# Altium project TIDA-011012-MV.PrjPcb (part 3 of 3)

## Sheet TIDA-011012-MV Auxiliary Power.SchDoc
size 431 x 279 mm; Date: Not shown in title block; ApprovedBy: Not shown in title block; CheckedBy: Not shown in title block; Author: Not shown in title block; CompanyName: Not shown in title block; Engineer: Not shown in title block; Organization: Not shown in title block; Address1: Not shown in title block; Address2: Not shown in title block; Address3: Not shown in title block; Address4: Not shown in title block; DocumentNumber: 4; Revision: Use project parameter SCH_Rev; SheetNumber: 4; SheetTotal: 11; PageSetup: Record=PageOptions¦CenterHorizontal=True¦CenterVertical=True¦PrintScale=1.00¦XCorrection=1.00¦YCorrection=1.00¦PrintKind=0¦BorderSize=5000000¦LeftOffset=0¦BottomOffset=0¦Orientation=2¦PaperLength=1000¦PaperWidth=1000¦Scale=100¦PaperSource=15¦PrintQuality=600¦MediaType=1¦DitherType=10¦PaperKind=Letter¦PrintScaleMode=1
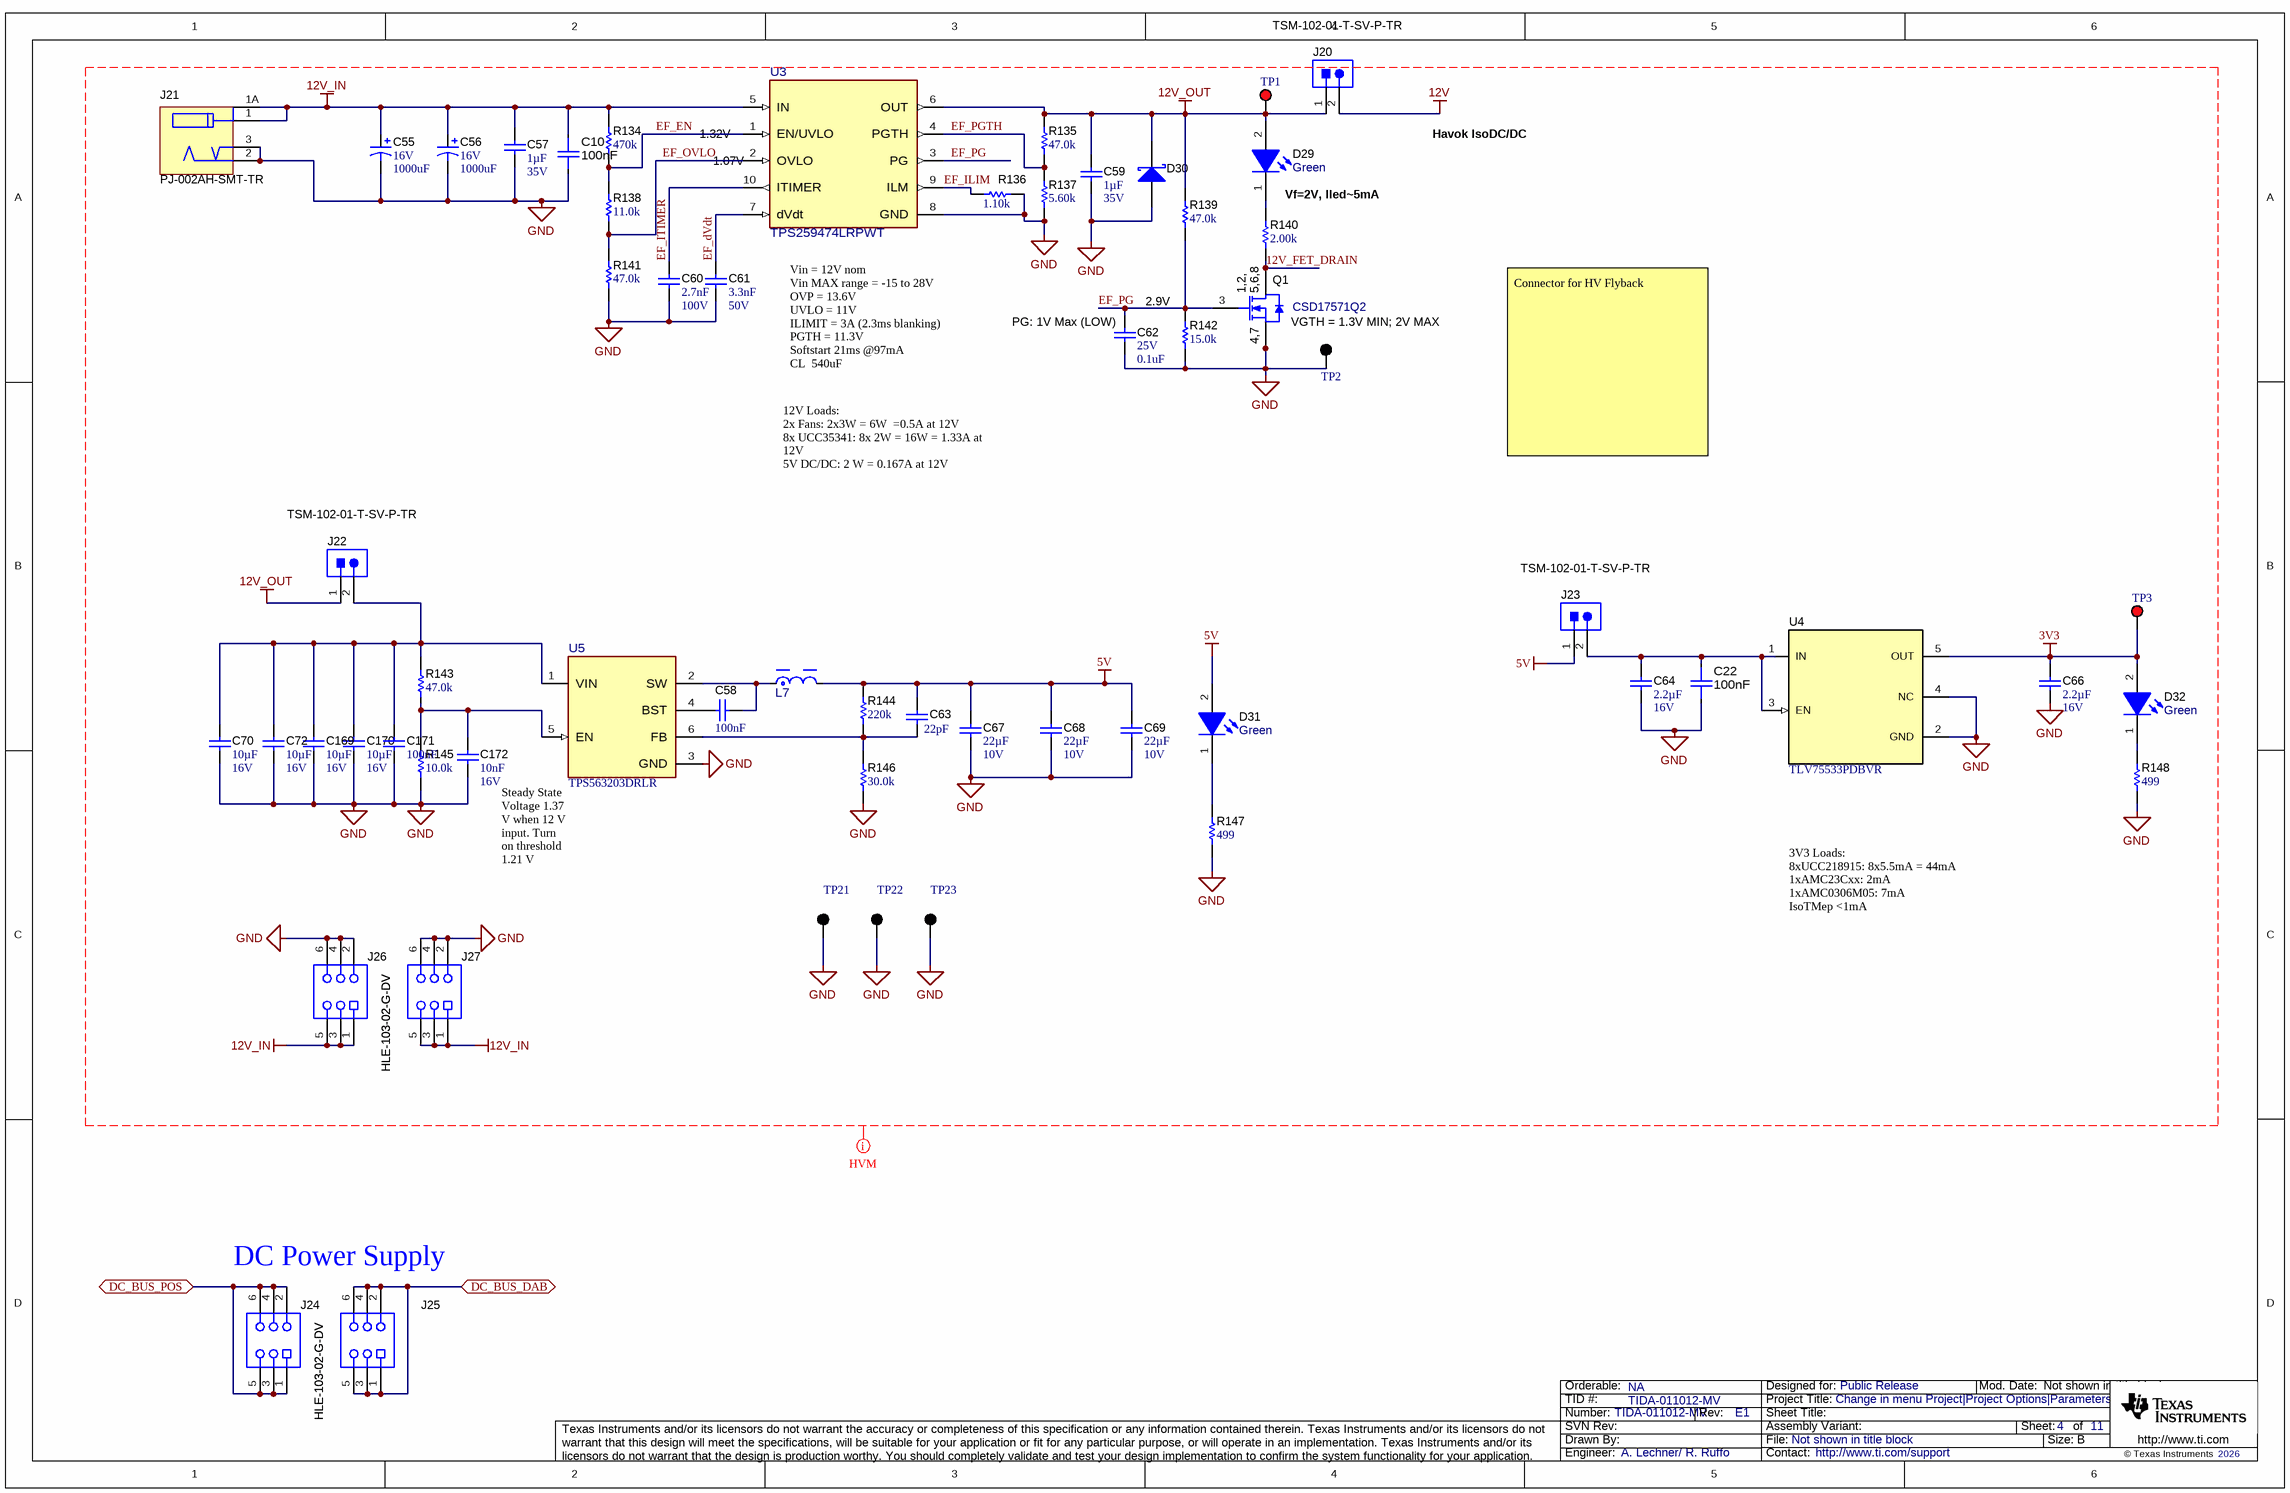
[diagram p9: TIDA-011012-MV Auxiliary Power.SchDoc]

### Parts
C10  Cap_F: 100nF  [FP-CL10B104KA8VPJC_0603-MFG]  (hidden comment: CL10B104KA8VPJC)
C22  Cap_F: 100nF  [FP-CL10B104KA8VPJC_0603-MFG]  (hidden comment: CL10B104KA8VPJC)
C55  VDC_V: 16V  ValueDisplayed: 1000uF  [CAPPR5-10x16]  (hidden comment: 16ZLJ1000MCE10X16)
C56  VDC_V: 16V  ValueDisplayed: 1000uF  [CAPPR5-10x16]  (hidden comment: 16ZLJ1000MCE10X16)
C57  Cap_F: 1µF  VDC_V: 35V  [0603]  (hidden comment: C1608X7R1V105K080AC)
C58  Cap_F: 100nF  [0603]  (hidden comment: 06033C104JAT2A)
C59  Cap_F: 1µF  VDC_V: 35V  [0603]  (hidden comment: C1608X7R1V105K080AC)
C60  Cap_F: 2.7nF  VDC_V: 100V  [0603]  (hidden comment: GRM188R72A272KA01D)
C61  Cap_F: 3.3nF  VDC_V: 50V  [0603]  (hidden comment: C0603X332K5RACTU)
C62  VDC_V: 25V  ValueDisplayed: 0.1uF  [0402L]  (hidden comment: GRM155R71E104KE14D)
C63  ValueDisplayed: 22pF  [0603]  (hidden comment: GRM1885C2A220JA01D)
C64  Cap_F: 2.2µF  VDC_V: 16V  [0603]  (hidden comment: EMK107BB7225KA-T)
C66  Cap_F: 2.2µF  VDC_V: 16V  [0603]  (hidden comment: EMK107BB7225KA-T)
C67  Cap_F: 22µF  VDC_V: 10V  [0805_HV]  (hidden comment: GRM21BZ71A226ME15L)
C68  Cap_F: 22µF  VDC_V: 10V  [0805_HV]  (hidden comment: GRM21BZ71A226ME15L)
C69  Cap_F: 22µF  VDC_V: 10V  [0805_HV]  (hidden comment: GRM21BZ71A226ME15L)
C70  Cap_F: 10µF  VDC_V: 16V  [0805_HV]  (hidden comment: EMK212BB7106KG-T)
C72  Cap_F: 10µF  VDC_V: 16V  [0805_HV]  (hidden comment: EMK212BB7106KG-T)
C169  Cap_F: 10µF  VDC_V: 16V  [0805_HV]  (hidden comment: EMK212BB7106KG-T)
C170  Cap_F: 10µF  VDC_V: 16V  [0805_HV]  (hidden comment: EMK212BB7106KG-T)
C171  Cap_F: 100nF  [0603]  (hidden comment: 06033C104JAT2A)
C172  Cap_F: 10nF  VDC_V: 16V  [0603]  (hidden comment: C0603C103K4RACTU)
D29  value Green  [WL-SMCW_GREEN]  (hidden comment: 150060VS75000)
D30  B330A-13-F  [SMA]  (value not drawn)
D31  value Green  [WL-SMCW_GREEN]  (hidden comment: 150060VS75000)
D32  value Green  [WL-SMCW_GREEN]  (hidden comment: 150060VS75000)
J20  TSM-102-01-T-SV-P-TR  [Samtec_TSM-102-01-T-SV-P-TR]
J21  PJ-002AH-SMT-TR  [CUI_PJ-002AH-SMT]
J22  TSM-102-01-T-SV-P-TR  [Samtec_TSM-102-01-T-SV-P-TR]
J23  TSM-102-01-T-SV-P-TR  [Samtec_TSM-102-01-T-SV-P-TR]
J24  HLE-103-02-G-DV  [Samtec_HLE-103-02-x-DV]
J25  HLE-103-02-G-DV  [Samtec_HLE-103-02-x-DV]
J26  HLE-103-02-G-DV  [Samtec_HLE-103-02-x-DV]
J27  HLE-103-02-G-DV  [Samtec_HLE-103-02-x-DV]
L7  74439324047  [FP-74439324047_SMD2-MFG]  (value not drawn)
Q1  CSD17571Q2  [DQK0006C]
R134  ValueDisplayed: 470k  [0603]  (hidden comment: RC0603FR-07470KL)
R135  ValueDisplayed: 47.0k  [0603]  (hidden comment: RC0603FR-0747KL)
R136  ValueDisplayed: 1.10k  [0603]  (hidden comment: RC0603FR-071K1L)
R137  ValueDisplayed: 5.60k  [0603]  (hidden comment: RC0603FR-075K6L)
R138  ValueDisplayed: 11.0k  [0603]  (hidden comment: RC0603FR-0711KL)
R139  ValueDisplayed: 47.0k  [0603]  (hidden comment: RC0603FR-0747KL)
R140  ValueDisplayed: 2.00k  [0603]  (hidden comment: RC0603FR-072KL)
R141  ValueDisplayed: 47.0k  [0603]  (hidden comment: RC0603FR-0747KL)
R142  ValueDisplayed: 15.0k  [0603]  (hidden comment: RC0603FR-0715KL)
R143  ValueDisplayed: 47.0k  [0603]  (hidden comment: RC0603FR-0747KL)
R144  ValueDisplayed: 220k  [0603]  (hidden comment: RC0603FR-07220KL)
R145  ValueDisplayed: 10.0k  [0603]  (hidden comment: RG1608P-103-B-T5)
R146  ValueDisplayed: 30.0k  [0603]  (hidden comment: RC0603FR-0730KL)
R147  ValueDisplayed: 499  [0603]  (hidden comment: CRCW0603499RFKEAC)
R148  ValueDisplayed: 499  [0603]  (hidden comment: CRCW0603499RFKEAC)
TP1  5010  [Keystone5010]  (value not drawn)
TP2  5011  [Keystone5011]  (value not drawn)
TP3  5010  [Keystone5010]  (value not drawn)
TP21  5011  [Keystone5011]  (value not drawn)
TP22  5011  [Keystone5011]  (value not drawn)
TP23  5011  [Keystone5011]  (value not drawn)
U3  TPS259474LRPWT  [RPW0010A-MFG]
U4  TLV75533PDBVR  [DBV0005A_N]
U5  TPS563203DRLR  [DRL0006A-MFG]

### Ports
DC_BUS_DAB (bidir), DC_BUS_POS (bidir)

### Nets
3V3: C66.1 D32.2(A) TP3.1 U4.5(OUT)
5V: C63.1 C67.1 C68.1 C69.1 D31.2(A) J23.1 L7.2 R144.2
12V: J20.2
12V_IN: C10.1 C55.1(+) C56.1(+) C57.1 J21.1 J21.1A J26.1 J26.3 J26.5 J27.1 J27.3 J27.5 R134.2 U3.5(IN)
12V_OUT: C59.1 D29.2(A) D30.1(K) J20.1 J22.1 R135.2 R139.2 TP1.1 U3.6(OUT)
GND: C10.2 C22.2 C55.2(-) C56.2(-) C57.2 C59.2 C60.2 C61.2 C62.2 C64.2 C66.2 C67.2 C68.2 C69.2 C70.2 C72.2 C169.2 C170.2 C171.1 C172.2 D30.2(A) J21.2 J21.3 J26.2 J26.4 J26.6 J27.2 J27.4 J27.6 Q1.4(S) Q1.7(S) R136.1 R137.1 R141.1 R142.1 R145.2 R146.1 R147.1 R148.1 TP2.1 TP21.1 TP22.1 TP23.1 U3.8(GND) U4.2(GND) U4.4(NC) U5.3(GND)
12V_FET_DRAIN: Q1.1(D) Q1.2(D) Q1.5(D) Q1.6(D) Q1.8(D) R140.1
DC_BUS_DAB: J25.1 J25.2 J25.3 J25.4 J25.5 J25.6 ; port DC_BUS_DAB
DC_BUS_POS: J24.1 J24.2 J24.3 J24.4 J24.5 J24.6 ; port DC_BUS_POS
EF_dVdt: C61.1 U3.7(dVdt)
EF_EN: R134.1 R138.2 U3.1(EN/UVLO)
EF_ILIM: R136.2 U3.9(ILM)
EF_ITIMER: C60.1 U3.10(ITIMER)
EF_OVLO: R138.1 R141.2 U3.2(OVLO)
EF_PG: C62.1 Q1.3(G) R139.1 R142.2 U3.3(PG)
EF_PGTH: R135.1 R137.2 U3.4(PGTH)
NetC22_1: C22.1 C64.1 J23.2 U4.1(IN) U4.3(EN)
NetC58_1: C58.1 U5.4(BST)
NetC58_2: C58.2 L7.1 U5.2(SW)
NetC63_2: C63.2 R144.1 R146.2 U5.6(FB)
NetC70_1: C70.1 C72.1 C169.1 C170.1 C171.2 J22.2 R143.2 U5.1(VIN)
NetC172_1: C172.1 R143.1 R145.1 U5.5(EN)
NetD29_1: D29.1(K) R140.2
NetD31_1: D31.1(K) R147.2
NetD32_1: D32.1(K) R148.2

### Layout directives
net class HVM: 3V3, 5V, 12V, 12V_FET_DRAIN, 12V_IN, 12V_OUT, EF_dVdt, EF_EN, EF_ILIM, EF_ITIMER, EF_OVLO, EF_PG, EF_PGTH, GND

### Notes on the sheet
- (near U3) 1.32V
- (near U3) 1.07V
- Havok IsoDC/DC
- Vf=2V, Iled~5mA
- 2.9V
- Vin = 12V nom
  Vin MAX range = -15 to 28V
  OVP = 13.6V
  UVLO = 11V
  ILIMIT = 3A (2.3ms blanking)
  PGTH = 11.3V
  Softstart 21ms @97mA
  CL  540uF
- (near C62) PG: 1V Max (LOW)
- VGTH = 1.3V MIN; 2V MAX
- 12V Loads:
  2x Fans: 2x3W = 6W  =0.5A at 12V
  8x UCC35341: 8x 2W = 16W = 1.33A at 12V
  5V DC/DC: 2 W = 0.167A at 12V
- Connector for HV Flyback
- (near U5) Steady State Voltage 1.37 V when 12 V input. Turn on threshold 1.21 V
- 3V3 Loads:
  8xUCC218915: 8x5.5mA = 44mA
  1xAMC23Cxx: 2mA
  1xAMC0306M05: 7mA
  IsoTMep <1mA
- DC Power Supply

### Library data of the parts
C10 C22 = CMP-0121051-1: Automotive CAP, 100㎋, 25V, ±10%, X7R, 0603, 5mm Bending; Manufacturer: Samsung; AEC Grade: Grade 1; AEC Qualified: Yes; SizeZ_mm: 0.9mm; TempCo: 15%; Value: 100nF
C55 C56 = CMP-0010289-1: CAP, AL, 1000 uF, 16 V, +/- 20%, TH; Manufacturer: Rubycon; TaMin_C: -40°C; Polarized: Y; SizeAreaWB_mm2: 144; Value1: Unknown; U/M: EA; Value: 1000uF; TaMax_C: 105°C; SizeZ_mm: 17.5; SizeX_mm: 10; Cap_Case: 10x16; SizeArea_mm2: 100; CompType: Capacitor; AEC Qualified: N; Cap_F: 1mF; AEC Category: Q200
C57 C59 = CMP-0007052-4: CAP, CERM, 1 uF, 35 V, +/- 10%, X7R, 0603; Manufacturer: TDK; TaMin_C: -55°C; Polarized: N; SizeAreaWB_mm2: 4.68; Value1: Unknown; U/M: EA; Value: 1uF; TaMax_C: 125°C; SizeZ_mm: 1; SizeX_mm: 1.6; SizeY_mm: 0.8; SizeArea_mm2: 1.28; AEC Category: Q200
C58 C171 = CMP-0006752-5: CAP, CERM, 0.1 uF, 25 V, +/- 5%, X7R, 0603; Manufacturer: AVX; TaMin_C: -55°C; ESR_ohm: 0.05; Polarized: N; SizeAreaWB_mm2: 4.68; Value1: 0.05 ohm; U/M: EA; Value: 0.1uF; TaMax_C: 125°C; SizeZ_mm: 1; SizeX_mm: 1.6; SizeY_mm: 0.8; Value2: 25V; SizeArea_mm2: 1.28; AEC Category: Q200
C60 = CMP-0007477-4: CAP, CERM, 2700 pF, 100 V, +/- 10%, X7R, 0603; Manufacturer: MuRata; TaMin_C: -55°C; Polarized: N; SizeAreaWB_mm2: 4.68; Value1: Unknown; U/M: EA; Value: 2700pF; TaMax_C: 125°C; SizeZ_mm: 1; SizeX_mm: 1.6; SizeY_mm: 0.8; SizeArea_mm2: 1.28; AEC Category: Q200
C61 = CMP-0006985-4: CAP, CERM, 3300 pF, 50 V, +/- 10%, X7R, 0603; Manufacturer: Kemet; TaMin_C: -55°C; Polarized: N; SizeAreaWB_mm2: 4.68; Value1: Unknown; U/M: EA; Value: 3300pF; TaMax_C: 125°C; SizeZ_mm: 1; SizeX_mm: 1.6; SizeY_mm: 0.8; SizeArea_mm2: 1.28; AEC Category: Q200
C62 = CMP-0006659-2: CAP, CERM, 0.1 uF, 25 V, +/- 10%, X7R, 0402; Manufacturer: MuRata; TaMin_C: -55°C; Polarized: N; SizeAreaWB_mm2: 3; Value1: Unknown; U/M: EA; Value: 0.1uF; TaMax_C: 125°C; SizeZ_mm: 0.6; SizeX_mm: 1; SizeY_mm: 0.5; Cap_Case: 0402; Cap_F: 100nF; AEC Category: Q200
C63 = CMP-0007255-4: CAP, CERM, 22 pF, 100 V, +/- 5%, C0G/NP0, 0603; Manufacturer: MuRata; TaMin_C: -55°C; Polarized: N; SizeAreaWB_mm2: 4.68; Value1: Unknown; U/M: EA; Value: 22pF; TaMax_C: 125°C; SizeZ_mm: 1; SizeX_mm: 1.6; SizeY_mm: 0.8; Value2: 100V; SizeArea_mm2: 1.28; AEC Category: Q200
C64 C66 = CMP-0007121-4: CAP, CERM, 2.2 uF, 16 V, +/- 10%, X7R, 0603; Manufacturer: Taiyo Yuden; TaMin_C: -55°C; Polarized: N; SizeAreaWB_mm2: 4.68; Value1: Unknown; U/M: EA; Value: 2.2uF; TaMax_C: 125°C; SizeZ_mm: 1; SizeX_mm: 1.6; SizeY_mm: 0.8; SizeArea_mm2: 1.28; AEC Category: Q200
C67-C69 = CMP-0008377-2: CAP, CERM, 22 uF, 10 V, +/- 20%, X7R, 0805; Manufacturer: MuRata; SizeY_mm: 1.25; Cap_Case: 0805; SizeArea_mm2: 2.5; AEC Qualified: N; AEC Category: Q200; ValueDisplayed: 22uF; TaMin_C: -55°C; SizeAreaWB_mm2: 6.75; Value1: Unknown; U/M: EA; Value: 22uF; TaMax_C: 125°C; SizeZ_mm: 1.45; SizeX_mm: 2
C70 C72 C169 C170 = CMP-0085283-1: CAP, CERM, 10 µF, 16 V,+/- 10%, X7R, 0805; Manufacturer: Taiyo Yuden; TaMin_C: -55°C; AEC Qualified: N; U/M: EA; TaMax_C: 125°C; SizeAreaWB_mm2: 6.75; SizeZ_mm: 1.45; Value: 10uF; SizeY_mm: 1.25; SizeArea_mm2: 2.5; AEC Category: Q200; SizeX_mm: 2; Cap_Case: 0805
C172 = CMP-0006853-4: CAP, CERM, 0.01 uF, 16 V, +/- 10%, X7R, 0603; Manufacturer: Kemet; TaMin_C: -55°C; Polarized: N; SizeAreaWB_mm2: 4.68; Value1: Unknown; U/M: EA; Value: 0.01uF; TaMax_C: 125°C; SizeZ_mm: 1; SizeX_mm: 1.6; SizeY_mm: 0.8; SizeArea_mm2: 1.28; AEC Category: Q200
D29 D31 D32 = CMP-0002894-2: LED, Green, SMD; Manufacturer: Wurth Elektronik; Type: AlInGaP; Value2: 2V; Io_A: 20mA; Value1: W
D30 = CMP-0028350-2: Diode, Schottky, 30 V, 3 A, SMA; Manufacturer: Diodes Inc.; Io_A: 3A; SizeZ_mm: 2.87; SizeAreaWB_mm2: 37.3428; Value: 30V; TJmax_C: 125°C; Green_Lifecycle: Active; SizeY_mm: 2.92; Vf_V: 500mV; Green_REACh: Passed; SizeArea_mm2: 16.3228; AEC Category: Q101; Value2: 0.5V; SizeX_mm: 5.59; RJC_CperW: 25
J20 J22 J23 = CMP-0075491-1: Header, 100mil, 2x1, Tin, SMD; Manufacturer: Samtec; Pitch_mm: 2.54; Gender: Male; Cert_CSA: Y; Current_A: 5.4A; Voltage_V: 475V; CT: False; Shrouded: N; Row_Count: 1; CNHeader: True
J21 = CMP-0075012-1: Power Jack, SMT; Manufacturer: CUI Inc.; Green_Lifecycle: Not Set; Green_REACh: Incomplete; CNHeader: False
J24-J27 = CMP-0082272-1: Receptacle, 2.54mm, 3x2, Gold, SMT; Manufacturer: Samtec; Pitch_mm: 2.54; Gender: Female; Cert_UL: Y; Voltage_V: 400V; Current_A: 4.1A; Row_Count: 2; CompType: Socket Strip
L7 = CMP-0128921-1: 4.7 µH Shielded Molded Inductor 5.3 A 36.96mOhm Max Nonstandard; Manufacturer: Wurth; AEC Grade: Grade 1; AEC Qualified: Yes; DCR_ohm: 36.96m; Ind_H: 4.7µH; Irms: 5.3A; Isat: 2.8A; Material: Iron; SizeZ_mm: 3.2mm; Value: 4.7uH; Self Resonant Frequency: 28MHz; Shrouded: true; TaMax_C: +85°C; TaMin_C: -40°C; Test Frequency: 100kHz; Tolerance_%: 20%
Q1 = CMP-0000585-1: MOSFET, N-CH, 30 V, 22 A, DQK0006C (WSON-6); Alternate Manufacturer: None; Manufacturer: Texas Instruments; SizeZ_mm: 0.8; ChType: N; Value2: 2.4 nC; Value1: 0.02; VdsMax_V: 30V; SizeX_mm: 2; Vgs_V: 20V; Value: 30V; Rdson45_ohm: 0.029; SizeArea_mm2: 4; AEC Category: Q101; IdsMax_A: 22A; SizeAreaWB_mm2: 9; U/M: EA; QgTyp_nC: 2.4
R134 = CMP-0023128-4: RES, 470 k, 1%, 0.1 W, 0603; Manufacturer: Yageo; Power_W: 100mW; TempCo: 100 ppm/C; Value: 470k; SizeX_mm: 1.6; SizeY_mm: 0.8; SizeZ_mm: 1; Value2: 0.1W; SizeArea_mm2: 1.28; AEC Qualified: N; VDC_V: 75V; AEC Category: Q200; SizeAreaWB_mm2: 4.68
R135 R139 R141 R143 = CMP-0023133-5: RES, 47.0 k, 1%, 0.1 W, 0603; Manufacturer: Yageo; Power_W: 100mW; TempCo: 100 ppm/C; Value_Code: 47k0; Value: 47.0k; Res_ohm: 47k; SizeX_mm: 1.6; SizeY_mm: 0.8; SizeZ_mm: 1; Value2: 0.1W; SizeArea_mm2: 1.28; AEC Qualified: N; VDC_V: 75V; AEC Category: Q200; SizeAreaWB_mm2: 4.68
R136 = CMP-0022870-5: RES, 1.10 k, 1%, 0.1 W, 0603; Manufacturer: Yageo; Power_W: 100mW; TempCo: 100 ppm/C; Value_Code: 1k10; Value: 1.10k; EIA_Code: E96; Res_ohm: 1.1k; SizeX_mm: 1.6; SizeY_mm: 0.8; SizeZ_mm: 1; Value2: 0.1W; SizeArea_mm2: 1.28; AEC Qualified: N; VDC_V: 75V; AEC Category: Q200; SizeAreaWB_mm2: 4.68
R137 = CMP-0023203-5: RES, 5.60 k, 1%, 0.1 W, 0603; Manufacturer: Yageo; Power_W: 100mW; TempCo: 100 ppm/C; Value_Code: 5k60; Value: 5.60k; Res_ohm: 5.6k; SizeX_mm: 1.6; SizeY_mm: 0.8; SizeZ_mm: 1; Value2: 0.1W; SizeArea_mm2: 1.28; AEC Qualified: N; VDC_V: 75V; AEC Category: Q200; SizeAreaWB_mm2: 4.68
R138 = CMP-0022763-5: RES, 11.0 k, 1%, 0.1 W, 0603; Manufacturer: Yageo; Power_W: 100mW; TempCo: 100 ppm/C; Value_Code: 11k0; Value: 11.0k; EIA_Code: E96; Res_ohm: 11k; SizeX_mm: 1.6; SizeY_mm: 0.8; SizeZ_mm: 1; Value2: 0.1W; SizeArea_mm2: 1.28; AEC Qualified: N; VDC_V: 75V; AEC Category: Q200; SizeAreaWB_mm2: 4.68
R140 = CMP-0023000-5: RES, 2.00 k, 1%, 0.1 W, 0603; Manufacturer: Yageo; Power_W: 100mW; TempCo: 100 ppm/C; Value_Code: 2k00; Value: 2.00k; EIA_Code: E96; Res_ohm: 2k; SizeX_mm: 1.6; SizeY_mm: 0.8; SizeZ_mm: 1; Value2: 0.1W; SizeArea_mm2: 1.28; AEC Qualified: N; VDC_V: 75V; AEC Category: Q200; SizeAreaWB_mm2: 4.68
R142 = CMP-0022816-5: RES, 15.0 k, 1%, 0.1 W, 0603; Manufacturer: Yageo; Power_W: 100mW; TempCo: 100 ppm/C; Value_Code: 15k0; Value: 15.0k; EIA_Code: E96; Res_ohm: 15k; SizeX_mm: 1.6; SizeY_mm: 0.8; SizeZ_mm: 1; Value2: 0.1W; SizeArea_mm2: 1.28; AEC Qualified: N; VDC_V: 75V; AEC Category: Q200; SizeAreaWB_mm2: 4.68
R144 = CMP-0022917-4: RES, 220 k, 1%, 0.1 W, 0603; Manufacturer: Yageo; Power_W: 100mW; TempCo: 100 ppm/C; Value: 220k; SizeX_mm: 1.6; SizeY_mm: 0.8; SizeZ_mm: 1; Value2: 0.1W; SizeArea_mm2: 1.28; AEC Qualified: N; VDC_V: 75V; AEC Category: Q200; SizeAreaWB_mm2: 4.68
R145 = CMP-0023404-3: RES, 10.0 k, 0.1%, 0.1 W, 0603; Manufacturer: Susumu Co Ltd; Power_W: 100mW; TempCo: 25 ppm/C; Value_Code: 10k0; U/M: EA; Value: 10.0k; EIA_Code: E192; Res_ohm: 10k; SizeX_mm: 1.6; SizeY_mm: 0.8; SizeZ_mm: 1; Value2: 0.1W; SizeArea_mm2: 1.28; VDC_V: 75V; AEC Category: Q200
R146 = CMP-0023020-5: RES, 30.0 k, 1%, 0.1 W, 0603; Manufacturer: Yageo; Power_W: 100mW; TempCo: 100 ppm/C; Value_Code: 30k0; Value: 30.0k; Res_ohm: 30k; SizeX_mm: 1.6; SizeY_mm: 0.8; SizeZ_mm: 1; Value2: 0.1W; SizeArea_mm2: 1.28; AEC Qualified: N; VDC_V: 75V; AEC Category: Q200; SizeAreaWB_mm2: 4.68
R147 R148 = CMP-0082532-1: RES, 499, 1%, 0.1 W, 0603; Manufacturer: Vishay-Dale; Power_W: 100mW; TempCo: 100 ppm/C; SizeAreaWB_mm2: 4.68; Value_Code: 499R; Value: 499; EIA_Code: E96; SizeX_mm: 1.6; SizeY_mm: 0.8; SizeZ_mm: 1; Value2: 0.1W; SizeArea_mm2: 1.28; AEC Qualified: N; VDC_V: 75V; AEC Category: Q200
TP1 TP3 = CMP-0055147-2: Test Point, Multipurpose, Red, TH; Manufacturer: Keystone Electronics; CT: TRUE; ContactFinish: Silver; Green_Lifecycle: Active; CNHeader: FALSE; Green_REACh: Passed
TP2 TP21-TP23 = CMP-0055148-2: Test Point, Multipurpose, Black, TH; Manufacturer: Keystone Electronics; CNHeader: FALSE; ContactFinish: Silver; Green_REACh: Passed; Green_Lifecycle: Active; CT: TRUE
U3 = CMP-0088329-1: 2.7- 23V, 5.5 A, 28 mΩ Reverse Current Blocking eFuse with Input Reverse Polarity Protection; Manufacturer: Texas Instruments; AEC Qualified: No; Nominal Supply Current: 0.5-6A; Threshold Voltage: 1.2/1.1V; Standoff Height: 0mm; Number Of Rails Monitored: 1; SizeZ_mm: 1mm; Min Supply Voltage: 2.7V; Reset Type: Active Low; TJmax_C: +125°C; Output Voltage: 42V
U4 = CMP-0074640-3: 500-mA, Low IQ, Small Size, Low Dropout Regulator, DBV0005A (SOT-23-5); Manufacturer: Texas Instruments; SizeX_mm: 2.8; SizeY_mm: 2.9; CompType: IC; SizeZ_mm: 1.45; SizeArea_mm2: 8.12; SizeAreaWB_mm2: 14.82; AEC Category: Q200; AEC Qualified: N
U5 = CMP-0047826-1: 4.2-V to 17-V Input, 3-A Synchronous Buck Converter in SOT563; Manufacturer: Texas Instruments; SizeZ_mm: 0.6mm; AEC Qualified: No; Max Duty Cycle: 95%; Max Supply Voltage: 17V; Min Supply Voltage: 4.2V; Nominal Supply Current: 110uA; Number Of Outputs: 1; Output Type: AdjustableProgrammable; Output Voltage: 0.6-7V; Standoff Height: 0mm; Switching Frequency: 600kHz; TJmax_C: +125°C

## Sheet TIDA-011012-MV_Hardware.SchDoc
size 431 x 279 mm; Date: Not shown in title block; ApprovedBy: Not shown in title block; CheckedBy: Not shown in title block; Author: Not shown in title block; CompanyName: Not shown in title block; Engineer: Not shown in title block; Organization: Not shown in title block; Address1: Not shown in title block; Address2: Not shown in title block; Address3: Not shown in title block; Address4: Not shown in title block; DocumentNumber: 5; Revision: Use project parameter SCH_Rev; SheetNumber: 5; SheetTotal: 11; PageSetup: Record=PageOptions¦CenterHorizontal=True¦CenterVertical=True¦PrintScale=1.00¦XCorrection=1.00¦YCorrection=1.00¦PrintKind=0¦BorderSize=5000000¦LeftOffset=0¦BottomOffset=0¦Orientation=2¦PaperLength=1000¦PaperWidth=1000¦Scale=100¦PaperSource=15¦PrintQuality=600¦MediaType=1¦DitherType=10¦PaperKind=Letter¦PrintScaleMode=1
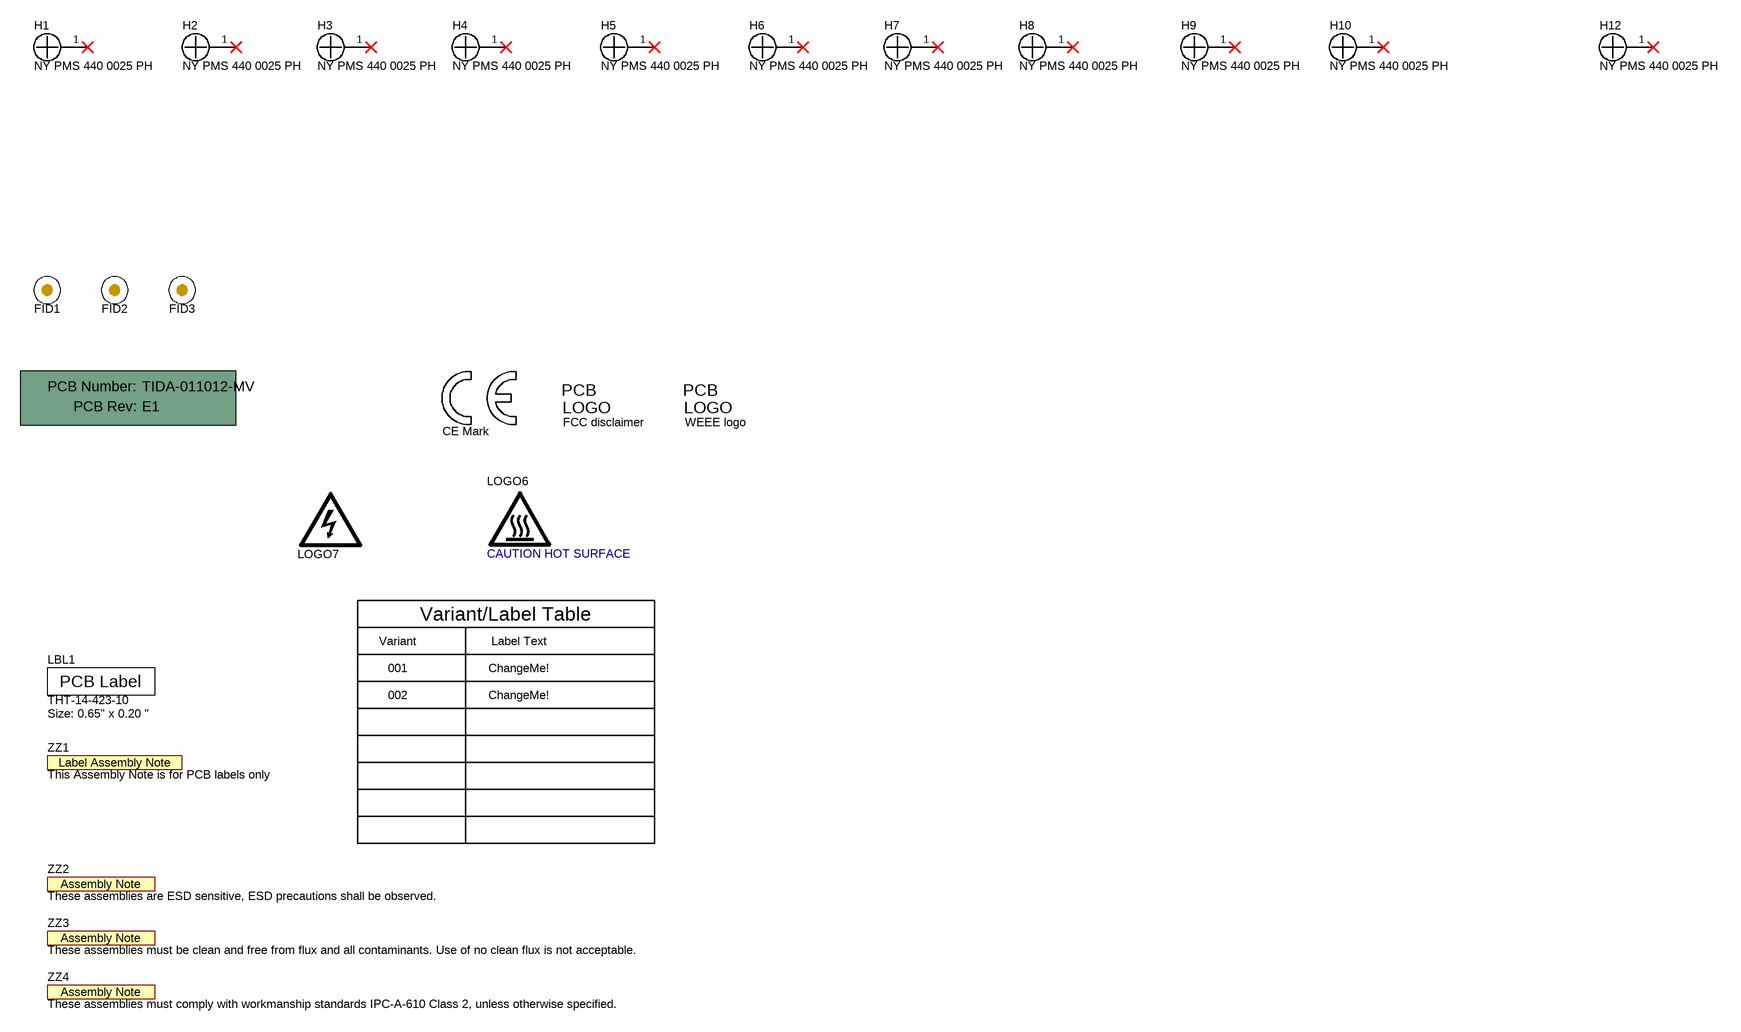
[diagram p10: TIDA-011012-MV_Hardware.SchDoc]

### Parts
!PCB1  Printed Circuit Board  (value not drawn)  (mechanical)
FID1  Fiducial  [Fiducial10-20]  (value not drawn)
FID2  Fiducial  [Fiducial10-20]  (value not drawn)
FID3  Fiducial  [Fiducial10-20]  (value not drawn)
H1  NY PMS 440 0025 PH  [NY PMS 440 0025 PH]
H2  NY PMS 440 0025 PH  [NY PMS 440 0025 PH]
H3  NY PMS 440 0025 PH  [NY PMS 440 0025 PH]
H4  NY PMS 440 0025 PH  [NY PMS 440 0025 PH]
H5  NY PMS 440 0025 PH  [NY PMS 440 0025 PH]
H6  NY PMS 440 0025 PH  [NY PMS 440 0025 PH]
H7  NY PMS 440 0025 PH  [NY PMS 440 0025 PH]
H8  NY PMS 440 0025 PH  [NY PMS 440 0025 PH]
H9  NY PMS 440 0025 PH  [NY PMS 440 0025 PH]
H10  NY PMS 440 0025 PH  [NY PMS 440 0025 PH]
H12  NY PMS 440 0025 PH  [NY PMS 440 0025 PH]
LBL1  THT-14-423-10  Note: Size: 0.65" x 0.20 "  [Label_650x200]
Logo1  CE Mark  [CE_Mark_5mm]  (no BOM)
Logo3  FCC disclaimer  [FCC_disclaimer]  (no BOM)
Logo4  WEEE logo  [WEEE_Minimum]  (no BOM)
LOGO6  CAUTION HOT SURFACE  [IEC_HotSurface_Medium]  (no BOM)
LOGO7  DANGER HIGH VOLTAGE  [IEC_HighVoltage_Medium]  (value not drawn)  (no BOM)
ZZ1  This Assembly Note is for PCB labels only  [AssemblyNoteLabel]  (no BOM)
ZZ2  These assemblies are ESD sensitive, ESD precautions shall be observed.  [AssemblyNote]  (no BOM)
ZZ3  These assemblies must be clean and free from flux and all contaminants. Use of no clean flux is not acceptable.  [AssemblyNote]  (no BOM)
ZZ4  These assemblies must comply with workmanship standards IPC-A-610 Class 2, unless otherwise specified.  [AssemblyNote]  (no BOM)

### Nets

Not connected (* = marked no-connect by the designer): H1 1*; H2 1*; H3 1*; H4 1*; H5 1*; H6 1*; H7 1*; H8 1*; H9 1*; H10 1*; H12 1*

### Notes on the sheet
- Variant
- Variant/Label Table
- Label Text
- 001
- 002
- ChangeMe!

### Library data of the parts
!PCB1 = CMP-0003618-2: Manufacturer: Any; PartNumber: TIDA-011012-MV
FID1-FID3 = CMP-0077181-1: Fiducial mark.  There is nothing to buy or mount.
H1-H10 H12 = CMP-0003617-1: Machine Screw, Round, #4-40 x 1/4, Nylon, Philips panhead; Manufacturer: B&F Fastener Supply; CompType: Hardware
LBL1 = CMP-0003625-1: Thermal Transfer Printable Labels, 0.650" W x 0.200" H - 10,000 per roll; Manufacturer: Brady; CompType: Label
Logo1 = CMP-0074844-1: SymbolCreator: a0412235
Logo3 = CMP-0074847-1: FCC_disclaimer; Library Reference: Logo
Logo4 = CMP-0074769-1
LOGO6 = CMP-0074837-2: IEC 61010-1 Hot Surface Warning; Manufacturer: Texas Instruments; SymbolCreator: a0412235; AEC Category: Q200; CompType: IC
LOGO7 = CMP-0074835-1: IEC 61010-1 High Voltage Warning; SymbolCreator: a0412235; Lib Reference: IEC_HighVoltage
ZZ1 = CMP-0003616-3
ZZ2 = CMP-0077236-1
ZZ3 = CMP-0077237-1
ZZ4 = CMP-0077238-1

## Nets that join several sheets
3V3: TIDA-011012-MV Power Conversion (J13.3 J14.3 J15.3 J16.3), TIDA-011012-MV Fans and Temp Sense (12 pins), TIDA-011012-MV Optical Interface (9 pins), TIDA-011012-MV Communication (8 pins), TIDA-011012-MV AC IV Sensing (6 pins), TIDA-011012-MV DC IV Sensing (6 pins), TIDA-011012-MV Current Comparator (C113.1 C114.1 U12.8), TIDA-011012-MV Switch Node Hall Current Sensing (5 pins), TIDA-011012-MV Auxiliary Power (C66.1 D32.2 TP3.1 U4.5)
5V: TIDA-011012-MV Fans and Temp Sense (C146.1 U29.5), TIDA-011012-MV Optical Interface (9 pins), TIDA-011012-MV Communication (6 pins), TIDA-011012-MV AC IV Sensing (5 pins), TIDA-011012-MV DC IV Sensing (5 pins), TIDA-011012-MV Current Comparator (5 pins), TIDA-011012-MV Auxiliary Power (8 pins)
12V: TIDA-011012-MV Power Conversion (J13.1 J14.1 J15.1 J16.1), TIDA-011012-MV Auxiliary Power (J20.2)
12V_IN: TIDA-011012-MV Fans and Temp Sense (C122.1 D33.1 J28.2 J29.2), TIDA-011012-MV Auxiliary Power (14 pins)
GND: TIDA-011012-MV Power Conversion (12 pins), TIDA-011012-MV Fans and Temp Sense (23 pins), TIDA-011012-MV Optical Interface (24 pins), TIDA-011012-MV Communication (68 pins), TIDA-011012-MV AC IV Sensing (16 pins), TIDA-011012-MV DC IV Sensing (16 pins), TIDA-011012-MV Current Comparator (12 pins), TIDA-011012-MV Switch Node Hall Current Sensing (6 pins), TIDA-011012-MV Auxiliary Power (47 pins)
AC_BUF_PMW1: TIDA-011012-MV Power Conversion (J13.2), TIDA-011012-MV Communication (R75.2)
AC_BUF_PMW2: TIDA-011012-MV Power Conversion (J13.4), TIDA-011012-MV Communication (R76.2)
AC_BUF_PMW3: TIDA-011012-MV Power Conversion (J14.2), TIDA-011012-MV Communication (R80.2)
AC_BUF_PMW4: TIDA-011012-MV Power Conversion (J14.4), TIDA-011012-MV Communication (R84.2)
AC_FAULT_FET1: TIDA-011012-MV Power Conversion (J13.6), TIDA-011012-MV Communication (R97.1)
AC_FAULT_FET2: TIDA-011012-MV Power Conversion (J13.8), TIDA-011012-MV Communication (R110.1)
AC_FAULT_FET3: TIDA-011012-MV Power Conversion (J14.6), TIDA-011012-MV Communication (R113.1)
AC_FAULT_FET4: TIDA-011012-MV Power Conversion (J14.8), TIDA-011012-MV Communication (R124.1)
AC_GD_RDY: TIDA-011012-MV Power Conversion (J13.7 J14.7), TIDA-011012-MV Communication (R52.2 R79.1)
AC_GD_RST/EN: TIDA-011012-MV Power Conversion (J13.5 J14.5), TIDA-011012-MV Communication (R81.1)
CLK_MOD_AC: TIDA-011012-MV Communication (R101.1), TIDA-011012-MV AC IV Sensing (R169.2 U9.7 U10.7)
CLK_MOD_DC: TIDA-011012-MV Communication (R106.1), TIDA-011012-MV DC IV Sensing (R154.2 U6.7 U7.7)
DATA_I_AC: TIDA-011012-MV Communication (R95.1), TIDA-011012-MV AC IV Sensing (C97.1 R168.2)
DATA_I_DC: TIDA-011012-MV Communication (R100.1), TIDA-011012-MV DC IV Sensing (C78.1 R153.2)
DATA_V_AC: TIDA-011012-MV Communication (R96.1), TIDA-011012-MV AC IV Sensing (C106.1 R178.2)
DATA_V_DC: TIDA-011012-MV Communication (R105.1), TIDA-011012-MV DC IV Sensing (C87.1 R163.2)
DC_BUF_PMW1: TIDA-011012-MV Power Conversion (J15.2), TIDA-011012-MV Communication (R111.2)
DC_BUF_PMW2: TIDA-011012-MV Power Conversion (J15.4), TIDA-011012-MV Communication (R112.2)
DC_BUF_PMW3: TIDA-011012-MV Power Conversion (J16.2), TIDA-011012-MV Communication (R114.2)
DC_BUF_PMW4: TIDA-011012-MV Power Conversion (J16.4), TIDA-011012-MV Communication (R117.2)
DC_BUS_DAB: TIDA-011012-MV Power Conversion (18 pins), TIDA-011012-MV DC IV Sensing (18 pins), TIDA-011012-MV Auxiliary Power (6 pins)
DC_BUS_POS: TIDA-011012-MV Power Conversion (38 pins), TIDA-011012-MV DC IV Sensing (R155.1), TIDA-011012-MV Auxiliary Power (6 pins)
DC_FAULT_FET1: TIDA-011012-MV Power Conversion (J15.6), TIDA-011012-MV Communication (R57.2)
DC_FAULT_FET2: TIDA-011012-MV Power Conversion (J15.8), TIDA-011012-MV Communication (R68.2)
DC_FAULT_FET3: TIDA-011012-MV Power Conversion (J16.6), TIDA-011012-MV Communication (R78.2)
DC_FAULT_FET4: TIDA-011012-MV Power Conversion (J16.8), TIDA-011012-MV Communication (R86.2)
DC_GD_RDY: TIDA-011012-MV Power Conversion (J15.7 J16.7), TIDA-011012-MV Communication (R50.2 R82.1)
DC_GD_RST/EN: TIDA-011012-MV Power Conversion (J15.5 J16.5), TIDA-011012-MV Communication (R83.1)
DC_OC: TIDA-011012-MV Communication (R94.2), TIDA-011012-MV Switch Node Hall Current Sensing (U25.7)
DC_OC_CMP: TIDA-011012-MV Communication (R109.2), TIDA-011012-MV Current Comparator (C116.1 R183.2)
FAN_EN: TIDA-011012-MV Fans and Temp Sense (R187.1), TIDA-011012-MV Communication (R88.1)
FAN_PWM: TIDA-011012-MV Fans and Temp Sense (U29.2), TIDA-011012-MV Communication (R90.1)
FSIRXA_CLK: TIDA-011012-MV Optical Interface (R215.1), TIDA-011012-MV Communication (R71.2)
FSIRXA_D0: TIDA-011012-MV Optical Interface (R216.1), TIDA-011012-MV Communication (R69.2)
FSITXA_CLK: TIDA-011012-MV Optical Interface (C147.1 U26.5), TIDA-011012-MV Communication (R72.1)
FSITXA_D0: TIDA-011012-MV Optical Interface (C149.1 U27.5), TIDA-011012-MV Communication (R70.1)
GND_ISO_AC_SENS: TIDA-011012-MV Power Conversion (J5.1 R42.2 TP15.1), TIDA-011012-MV AC IV Sensing (18 pins)
I_DC_MINUS: TIDA-011012-MV Power Conversion (R41.4), TIDA-011012-MV DC IV Sensing (R152.1)
I_DC_POS: TIDA-011012-MV Power Conversion (R41.3), TIDA-011012-MV DC IV Sensing (R151.1)
I_HALL: TIDA-011012-MV Communication (R85.1), TIDA-011012-MV Switch Node Hall Current Sensing (C160.1 R199.2)
I_HALL_N: TIDA-011012-MV Power Conversion (R43.1), TIDA-011012-MV Switch Node Hall Current Sensing (U25.2)
I_HALL_P: TIDA-011012-MV Power Conversion (C173.1 C174.1 C175.1 C176.1), TIDA-011012-MV Switch Node Hall Current Sensing (U25.1)
I_SW_NEG: TIDA-011012-MV Power Conversion (R43.4), TIDA-011012-MV Current Comparator (13 pins)
I_SW_POS: TIDA-011012-MV Power Conversion (R43.3), TIDA-011012-MV Current Comparator (R182.1)
IAC_NEG: TIDA-011012-MV Power Conversion (R42.3), TIDA-011012-MV AC IV Sensing (R167.1)
IAC_POS: TIDA-011012-MV Power Conversion (R42.4), TIDA-011012-MV AC IV Sensing (R166.1)
NTC1_N: TIDA-011012-MV Power Conversion (MD1.T2), TIDA-011012-MV Fans and Temp Sense (R190.2 U16.3)
NTC1_P: TIDA-011012-MV Power Conversion (MD1.T1), TIDA-011012-MV Fans and Temp Sense (R218.1)
NTC2_N: TIDA-011012-MV Power Conversion (MD2.T2), TIDA-011012-MV Fans and Temp Sense (R192.2 U18.3)
NTC2_P: TIDA-011012-MV Power Conversion (MD2.T1), TIDA-011012-MV Fans and Temp Sense (R219.1)
PWM_SYNC_RX: TIDA-011012-MV Optical Interface (R217.1), TIDA-011012-MV Communication (R74.2)
PWM_SYNC_TX: TIDA-011012-MV Optical Interface (C151.1 U28.5), TIDA-011012-MV Communication (R73.2)
TEMP1: TIDA-011012-MV Fans and Temp Sense (C124.2 R186.1), TIDA-011012-MV Communication (R44.1)
TEMP2: TIDA-011012-MV Fans and Temp Sense (C127.2 R189.1), TIDA-011012-MV Communication (R56.1)
TEMP3: TIDA-011012-MV Fans and Temp Sense (C131.2 R191.1), TIDA-011012-MV Communication (R77.1)
TEMP4: TIDA-011012-MV Fans and Temp Sense (U16.1 U16.4), TIDA-011012-MV Communication (R51.1)
TEMP5: TIDA-011012-MV Fans and Temp Sense (U18.1 U18.4), TIDA-011012-MV Communication (R67.1)
VAC_POS: TIDA-011012-MV Power Conversion (D14.1 J11.1 MD1.AC2 TP19.1), TIDA-011012-MV AC IV Sensing (R170.1)

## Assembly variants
001: not fitted !PCB1 C4 C5 C6 C7 C8 C9 C16 C17 C18 C19 C20 C21 C55 C56 C173 C174 C175 C176 C177 C178 C179 C180 FID1 FID2 FID3 H1 H2 H3 H4 H5 H6 H7 H8 H9 H10 H12 H13 H14 H15 H16 LBL1 Logo1 Logo2 Logo3 Logo4 MD1 MD2 U19 U20 U21 U22 U23 U24 ZZ1 ZZ2 ZZ3 ZZ4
